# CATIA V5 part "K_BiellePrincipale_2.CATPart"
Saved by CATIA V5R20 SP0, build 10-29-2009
Part number: Bielle_principale_2
Bounding box of the stored display mesh (mm): x -665 to -75.005, y -279.606 to -5, z -253.803 to -35.005
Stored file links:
  G:\Khaled_CFAO_2011\ST2M\ST2M_GR2\jcoetard\Khaled\CAD_CATIA\K_BiellePrincipale_2.CATPart
  J:\Thinkmotion\Thinkmotion_COETARD\Maquette_catia\Maquette_catia_R20_Licence_education\jcharlescoetard.CATPRODUCT\Assemblage_Pince_Prehension_Mors_Paralleles.CATProduct
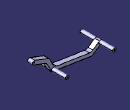
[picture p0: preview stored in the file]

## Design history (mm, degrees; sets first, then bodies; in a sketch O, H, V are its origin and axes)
Set1
  Plane1 "Plan_bielle_principale": linked copy from another document
  Point1 "Point.11": linked copy from another document
  Point2 "Point.8": linked copy from another document
  Point3 "Point.10": linked copy from another document
Body1 (main body)
  Sketch1 on Plane1, origin (0, -122.303, 0), H (-1, 0, 0), V (0, 0, 1)
    construction line L1 (90, -50) -> (204.738, -94.0206)
    point P1 (90, -50)
    point P2 (204.738, -94.0206)
    line L2 (95.373, -35.9953) -> (210.111, -80.0159)
    line L3 (180.0398, -100.6109) -> (84.627, -64.0047)
    arc A1 centre (204.738, -94.0206) radius 15 from (210.111, -80.0159) to (218.0112, -87.0332) cw
    arc A2 centre (90, -50) radius 15 from (84.627, -64.0047) to (95.373, -35.9953) cw
    construction line L4 (204.738, -94.0206) -> (250, -180)
    point P6 (204.738, -94.0206)
    point P7 (250, -180)
    line L5 (218.0112, -87.0332) -> (250.4137, -148.5848)
    line L6 (236.7268, -186.9874) -> (201.1068, -119.3237)
    reference projected point E1 (90, -50) from Point1
    reference projected point E2 (250, -180) from Point2
    construction line L7 (250, -180) -> (576, -231.225)
    point P10 (250, -180)
    point P11 (576, -231.225)
    line L8 (279.5997, -169.467) -> (556.5845, -212.9901)
    line L9 (573.6716, -246.0432) -> (247.6716, -194.8182)
    arc A3 centre (250, -180) radius 15 from (247.6716, -194.8182) to (236.7268, -186.9874) cw
    reference projected point E3 (250, -180) from Point2
    construction line L10 (576, -231.225) -> (650, -180)
    point P14 (576, -231.225)
    point P15 (650, -180)
    line L11 (585.5602, -206.3639) -> (641.4625, -167.6667)
    line L12 (658.5375, -192.3333) -> (584.5375, -243.5583)
    arc A4 centre (650, -180) radius 15 from (641.4625, -167.6667) to (658.5375, -192.3333) cw
    arc A5 centre (576, -231.225) radius 15 from (584.5375, -243.5583) to (573.6716, -246.0432) cw
    reference projected point E4 (650, -180) from Point3
    arc A6 centre (165.7117, -137.9566) radius 40 from (201.1068, -119.3237) to (180.0398, -100.6109) ccw
    point P21 (165.7117, -137.9566)
    arc A7 centre (285.8088, -129.9519) radius 40 from (250.4137, -148.5848) to (279.5997, -169.467) ccw
    point P24 (285.8088, -129.9519)
    arc A8 centre (562.7936, -173.475) radius 40 from (585.5602, -206.3639) to (556.5845, -212.9901) cw
    point P27 (562.7936, -173.475)
    reference projected point E5 (250, -180) from Point2
    distance L2 L3 = 30
    distance L5 L6 = 30
    distance L8 L9 = 30
    distance L11 L12 = 30
    radius A6 = 40
    radius A7 = 40
    radius A8 = 40
    distance P6 P21 = 58.7659
    distance P24 E5 = 61.5393
    distance P27 P14 = 59.2408
    tangency: A1 L2, A2 L2, A1 L3, A2 L3, A3 L8, A3 L9, A4 L11, A5 L11, A4 L12, A5 L12, A6 L6, A6 L3, A7 L5, A7 L8, A8 L11, A8 L8, L5 A1, L6 A3, L9 A5
    coincidence: P6 P2, P1 E1, P7 E2, P10 E3, P14 P11, P15 E4
  Pad1: profile Sketch1, direction (0, -1, 0), length 40
  Sketch2 on start face of Pad1, origin (-60, -122.303, -50), H (1, 0, 0), V (0, 0, -1)
    point P1 (-30, 0)
    reference projected point E1 (-30, 0) from Point1
    coincidence: E1 P1
  Hole1: placed by Sketch2, at (-90, -122.303, -50) direction (0, -1, 0), diameter 10, depth 50
  Sketch3 on start face of Pad1, origin (0, -122.303, 0), H (-1, 0, 0), V (0, 0, 1)
    circle A1 centre (250, -180) radius 15
    point P1 (250, -180)
    reference projected point E1 (250, -180) from Point2
    reference projected arc E2 centre (250, -180) radius 15 from (236.7268, -186.9874) to (247.6716, -194.8182) ccw from edge [face of Pad1 from Sketch1.A3 | start face of Pad1]
    circle A2 centre (650, -180) radius 15
    point P2 (650, -180)
    reference projected point E3 (650, -180) from Point3
    reference projected arc E4 centre (650, -180) radius 15 from (658.5375, -192.3333) to (641.4625, -167.6667) ccw from edge [face of Pad1 from Sketch1.A4 | start face of Pad1]
    coincidence: P1 E1, P2 E3
    tangency: A1 E2, A2 E4
  Pad2: profile Sketch3, direction (0, 1, 0), length 117.303
  Sketch4 on end face of Pad2, origin (-230, -5, -180), H (1, 0, 0), V (0, 0, -1)
    point P1 (-20, 0)
    reference projected point E1 (-20, 0) from Point2
    coincidence: E1 P1
  Hole2: placed by Sketch4, at (-250, -5, -180) direction (0, -1, 0), diameter 10, depth 200
  Sketch5 on end face of Pad2, origin (-580, -5, -180), H (1, 0, 0), V (0, 0, -1)
    point P1 (-70, 0)
    reference projected point E1 (-70, 0) from Point3
    coincidence: E1 P1
  Hole3: placed by Sketch5, at (-650, -5, -180) direction (0, -1, 0), diameter 10, depth 200
  Sketch6 on end face of Pad1, origin (0, -162.303, 0), H (1, 0, 0), V (0, 0, 1)
    circle A1 centre (-650, -180) radius 15
    point P1 (-650, -180)
    reference projected arc E1 centre (-650, -180) radius 15 from (-641.4625, -167.6667) to (-658.5375, -192.3333) ccw from edge [end face of Pad1 | face of Pad1 from Sketch1.A4]
    reference projected point E2 (-650, -180) from Point3
    circle A2 centre (-250, -180) radius 15
    point P2 (-250, -180)
    reference projected point E3 (-250, -180) from Point2
    reference projected arc E4 centre (-250, -180) radius 15 from (-247.6716, -194.8182) to (-236.7268, -186.9874) ccw from edge [end face of Pad1 | face of Pad2]
    tangency: E1 A1, A2 E4
    coincidence: P1 E2, E3 P2
  Pad3: profile Sketch6, direction (0, -1, 0), length 117.303
  Sketch7 on end face of Pad3, origin (-590, -279.606, -230), H (1, 0, 0), V (0, 0, 1)
    point P1 (-60, 50)
    reference projected point E1 (-60, 50) from Point3
    coincidence: E1 P1
  Hole4: placed by Sketch7, at (-650, -279.606, -180) direction (0, 1, 0), diameter 10, depth 200
  Sketch8 on end face of Pad3, origin (-220, -279.606, -230), H (1, 0, 0), V (0, 0, 1)
    point P1 (-30, 50)
    reference projected point E1 (-30, 50) from Point2
    coincidence: E1 P1
  Hole5: placed by Sketch8, at (-250, -279.606, -180) direction (0, 1, 0), diameter 10, depth 200
  Sketch9 on face of Pad1 from Sketch1.L9, origin (23.9068, 0, -152.1446), H (0, 1, 0), V (0.9879, 0, 0.1552)
    line L1 (-152.303, -274.9106) -> (-132.303, -274.9106)
    line L2 (-132.303, -274.9106) -> (-132.303, -604.9106)
    line L3 (-132.303, -604.9106) -> (-152.303, -604.9106)
    line L4 (-152.303, -604.9106) -> (-152.303, -274.9106)
    reference projected line E1 (-122.303, -273.3583) -> (-122.303, -603.3583) from edge [face of Pad1 from Sketch1.L9 | start face of Pad1]
    reference projected line E2 (-162.303, -273.3583) -> (-162.303, -603.3583) from edge [end face of Pad1 | face of Pad1 from Sketch1.L9]
    reference projected line E3 (-122.303, -274.9106) -> (-162.303, -274.9106) from edge [face of Pad2 | face of Pad1 from Sketch1.L9]
    reference projected line E4 (-122.303, -604.9106) -> (-162.303, -604.9106) from edge [face of Pad1 from Sketch1.L9 | face of Pad1 from Sketch1.A5]
    distance L2 E1 = 10
    distance L4 E2 = 10
    horizontal: L1 H, L3 H
    vertical: L2 V, L4 V
    coincidence: L1 E3, L3 E4
  Pad4: profile Sketch9, direction (0.1552, 0, -0.9879), length 8
  Fillet1: radius 1, on end face of Pad4
  Fillet2: radius 0.5, on edge [face of Pad1 from Sketch1.L9 | face of Pad4 from Sketch9.L4]; edge [face of Pad1 from Sketch1.L9 | face of Pad4 from Sketch9.L2]; edge [face of Pad4 from Sketch9.L3 | face of Pad1 from Sketch1.A5]; edge [face of Pad2 | face of Pad4 from Sketch9.L1]
  Fillet3: radius 2, on edge [end face of Pad1 | face of Pad1 from Sketch1.L9]
  Fillet4: radius 2, on edge [face of Pad1 from Sketch1.L9 | start face of Pad1]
